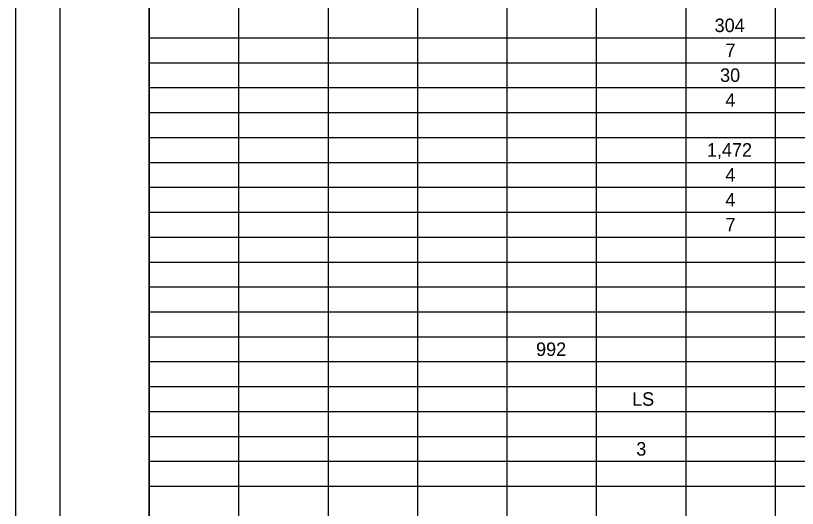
# Model space of a CAD drawing. Extents: x 0 to 34, y 0 to 22.
# Drawn here: x 0 to 8.78, y 10.89 to 16.43 of the extents above; entities that cross this region are included whole.
import ezdxf

# ---------------------------------------------------------------- set-up
doc = ezdxf.new("R2010")
doc.units = 0
for name, color, linetype in [('SH_Border', 7, 'Continuous'), ('SH_Cut_Line', 7, 'Continuous'), ('SH_Text', 7, 'Continuous')]:
    doc.layers.add(name, color=color, linetype=linetype)

msp = doc.modelspace()

# ---------------------------------------------------------------- linework, layer by layer
at = {"layer": 'SH_Border'}
for points in [[(0.5, 21.5), (1.5, 21.5), (1.5, 0.5), (0.5, 0.5)], [(1.5, 21.5), (33.5, 21.5), (33.5, 0.5), (1.5, 0.5)]]:
    msp.add_lwpolyline(points, close=True, dxfattribs=at)
at = {"layer": 'SH_Cut_Line'}
msp.add_lwpolyline([(0, 0), (34, 0), (34, 22), (0, 22)], close=True, dxfattribs=at)
at = {"layer": 'SH_Text'}
for p, q in [((1.5, 21.5), (1.5, 0.5)), ((2.5046, 20.94), (2.5046, 0.5)), ((3.5092, 20.94), (3.5092, 0.5)), ((4.5138, 20.94), (4.5138, 0.5)), ((5.5184, 20.94), (5.5184, 0.5)), ((6.5229, 20.94), (6.5229, 0.5)), ((7.5275, 20.94), (7.5275, 0.5)), ((8.5321, 20.94), (8.5321, 0.5)), ((1.5, 16.18), (32, 16.18)), ((1.5, 15.9), (32, 15.9)), ((1.5, 15.62), (32, 15.62)), ((1.5, 15.34), (32, 15.34)), ((1.5, 15.06), (32, 15.06)), ((1.5, 14.78), (32, 14.78)), ((1.5, 14.5), (32, 14.5)), ((1.5, 14.22), (32, 14.22)), ((1.5, 13.94), (32, 13.94)), ((1.5, 13.66), (32, 13.66)), ((1.5, 13.38), (32, 13.38)), ((1.5, 13.1), (32, 13.1)), ((1.5, 12.82), (32, 12.82)), ((1.5, 12.54), (32, 12.54)), ((1.5, 12.26), (32, 12.26)), ((1.5, 11.98), (32, 11.98)), ((1.5, 11.7), (32, 11.7)), ((1.5, 11.42), (32, 11.42)), ((1.5, 11.14), (32, 11.14))]:
    msp.add_line(p, q, dxfattribs=at)

# ---------------------------------------------------------------- texts
for s, height, p in [('304', 0.15153, (7.8519, 16.2442)), ('7', 0.1515, (7.9748, 15.9642)), ('30', 0.15153, (7.913, 15.6842)), ('4', 0.1515, (7.9728, 15.4042)), ('1,472', 0.15153, (7.7648, 14.8442)), ('4', 0.1515, (7.9728, 14.5642)), ('4', 0.1515, (7.9728, 14.2842)), ('7', 0.1515, (7.9748, 14.0042)), ('992', 0.15153, (5.8459, 12.6042)), ('LS', 0.15153, (6.9246, 12.0442)), ('3', 0.1515, (6.972, 11.4842))]:
    msp.add_text(s, height=height, dxfattribs=at).set_placement(p)

doc.saveas('drawing.dxf')
